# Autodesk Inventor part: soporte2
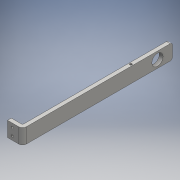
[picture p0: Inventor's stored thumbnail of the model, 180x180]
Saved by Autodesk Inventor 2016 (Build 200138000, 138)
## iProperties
Created: 2016-06
Part Number: soporte2
Material: Generic
Document SubType Name: Modeling
Designer: yesi alvarez
Mass: 21.1432 g
Surface Area: 111.336 cm^2
Volume: 21.1432 cm^3
Density: 1 g/cm^3
Appearance: Default
Author: yesi alvarez
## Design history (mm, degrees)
sketch "Sketch1"
  geometry: L1 (0, 0)-(0, 0); L2 (5, 5)-(5, 200); L3 (5, 200)-(0, 200); L4 (0, 200)-(0, 7); L5 (0, 0)-(-15, 0); L6 (-15, 0)-(-15, 5); L7 (-15, 5)-(-2, 5); A1 r 2 centre (-2, 7) between (-2, 5) and (0, 7); A2 r 5 centre (0, 5) between (0, 0) and (5, 5)
  constraints: 14 end point, 4 point on circle, 4 tangent, 3 parallel, 2 centre point, 2 horizontal, 2 perpendicular
  dimensions: "d0" = 5 distance of L3.end L2.end; "d3" = 5 distance of L5.end L6.end; "d4" = 2 radius of A1; "d5" = 5 radius of A2; "d25" = 200 vertical distance of L1.start L2.end
extrude "Extrusion1" new body sketch "Sketch1" distance "d6" = 20; taper "d7" = 0 deg
fillet "Fillet1" dims "d8" = 3
sketch "Sketch2"
  geometry: L1 (3, 193)-(17, 193) reference; C1 r 7.5 at (10, 173); 2 further points
  constraints: 1 centre point, 1 coincident
  dimensions: "d9" = 20 distance from line of point (10, 173) L1; "d10" = 15 diameter of C1
extrude "Extrusion2" cut sketch "Sketch2" distance "d11" = 20; taper "d12" = 0 deg
sketch "Sketch3"
  geometry: L1 (0, 0)-(13, 0) reference; L2 (13, -20)-(0, -20) reference; C1 r 1.5 at (6.5, -5); C2 r 1.5 at (6.5, -15); 3 further points
  constraints: 2 centre point, 2 coincident
  dimensions: "d15" = 5 distance from line of point (6.5, -5) L1; "d16" = 5 distance from line of L2 point (6.5, -15); "d17" = 3 diameter of C1; "d18" = 3 diameter of C2
extrude "Extrusion3" cut sketch "Sketch3" distance "d19" = 20; taper "d20" = 0 deg
thread "Thread2" dims "d21" = 10, "d22" = 0
thread "Thread3" dims "d23" = 10, "d24" = 0
sketch "Sketch4"
  geometry: L1 (0, 197)-(5, 197) reference; C1 r 1.5 at (2.5, 147); 2 further points
  constraints: 1 centre point, 1 coincident
  dimensions: "d26" = 50 distance from line of point (2.5, 147) L1; "d27" = 3 diameter of C1
extrude "Extrusion4" cut sketch "Sketch4" distance "d28" = 50; taper "d29" = 0 deg
thread "Thread4" dims "d30" = 10, "d31" = 0
body "Solid1"
